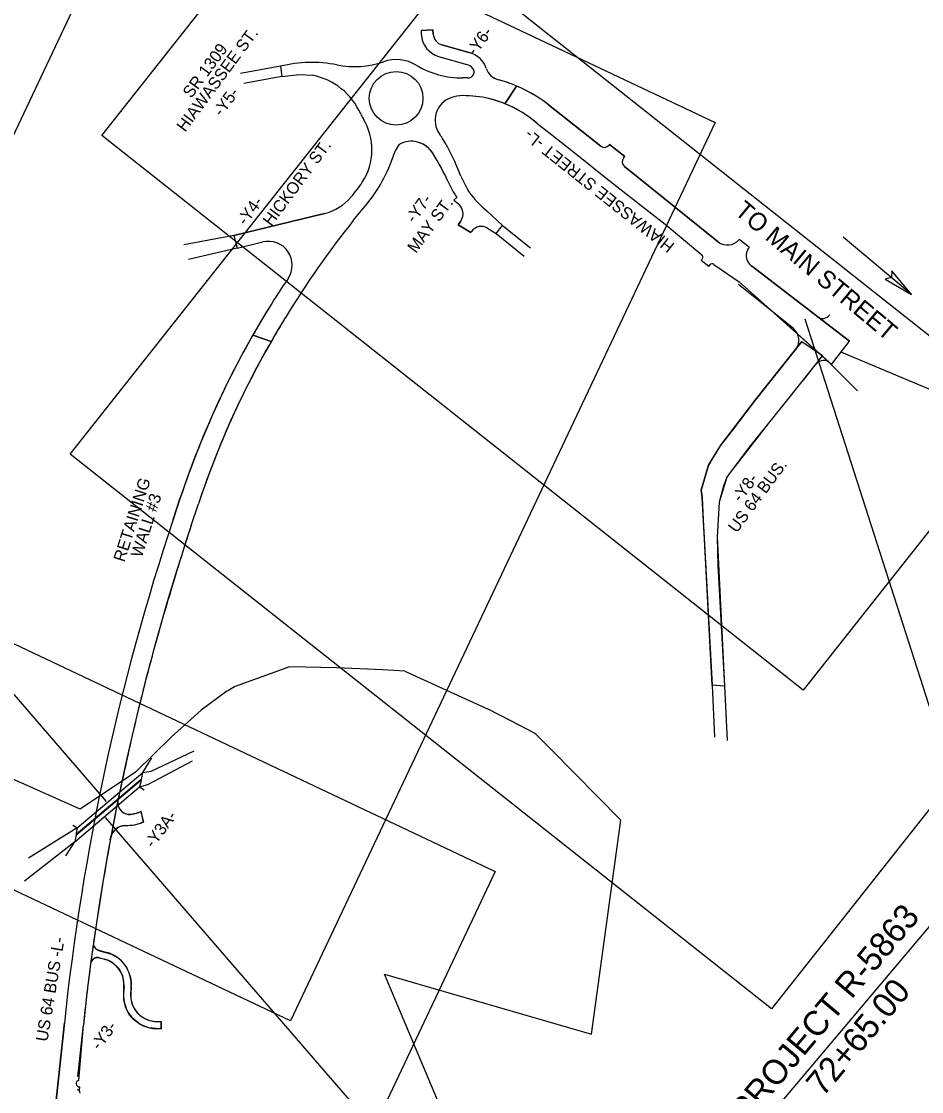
# Model space of a CAD drawing. Extents: x 555292 to 2368606, y 503623 to 1171444.
# Drawn here: x 2361051 to 2362561, y 1164815 to 1166609 of the extents above; entities that cross this region are included whole.
import ezdxf

# ---------------------------------------------------------------- set-up
doc = ezdxf.new("R2010")
doc.units = 0
for name, color, linetype in [('Exist Hydro Stream or Body of Water', 7, 'Continuous'), ('Exist Roads EOT', 7, 'Continuous'), ('Old_Level_48', 7, 'Continuous'), ('Prop DSN Text', 7, 'Continuous'), ('Prop EOT', 7, 'Continuous'), ('Prop Horizontal Alignment Station Label', 7, 'Continuous'), ('Prop Roadway Culvert', 7, 'Continuous'), ('Prop Shade Light', 7, 'Continuous'), ('Prop Terminator CELL', 7, 'Continuous'), ('Sheet Title CELL', 7, 'Continuous')]:
    doc.layers.add(name, color=color, linetype=linetype)

msp = doc.modelspace()

# ---------------------------------------------------------------- linework, layer by layer
at = {"layer": 'Exist Hydro Stream or Body of Water'}
for p, q in [((2361268.9, 1165352.1), (2361341, 1165386.3)), ((2361263.2, 1165330), (2361338.3, 1165369.6)), ((2361254.8, 1165349.8), (2361268.9, 1165352.1)), ((2361249.5, 1165325.7), (2361263.2, 1165330)), ((2361145, 1165257.1), (2361063.4, 1165206)), ((2361140.7, 1165233.8), (2361056.4, 1165167.9))]:
    msp.add_line(p, q, dxfattribs=at)
at = {"layer": 'Exist Roads EOT'}
for p, q in [((2361485.8, 1166534.3), (2361418.7, 1166522.2)), ((2361488.4, 1166517), (2361424.2, 1166505.6)), ((2361858.1, 1166267.1), (2361905.5, 1166229.8)), ((2361407.8, 1166250.5), (2361323.9, 1166235)), ((2361847.6, 1166253.7), (2361894.7, 1166216)), ((2361413, 1166229.1), (2361331.8, 1166210.2)), ((2362346.2, 1166094.3), (2362254.4, 1166168.4)), ((2362282.4, 1165974.1), (2362350, 1166059.3)), ((2362453.7, 1165990), (2362405.2, 1166038.7)), ((2362363.4, 1166008.1), (2362384.7, 1166035)), ((2362210.1, 1165496.3), (2362213.7, 1165409.2)), ((2362230.6, 1165494.8), (2362235, 1165403.4))]:
    msp.add_line(p, q, dxfattribs=at)
for centre, radius, start, end in [((2362395.4, 1166126.3), 15, 231.9272, 322.728), ((2362330.5, 1166074.8), 25, 321.5477, 51.0718), ((2362396.7, 1166026), 15, 44.846, 141.6227)]:
    msp.add_arc(centre, radius, start, end, dxfattribs=at)
at = {"layer": 'Old_Level_48'}
msp.add_line((2361694.7, 1165519.7), (2361834, 1165456.3), dxfattribs=at)
for points in [[(2361694.7, 1165519.7), (2361657.5, 1165522.1), (2361579.9, 1165525.5), (2361500.9, 1165527.2), (2361409.7, 1165494.3), (2361393.5, 1165484.8), (2361352.7, 1165454.5), (2361302.7, 1165408.9), (2361242.7, 1165350.5), (2361149.7, 1165288.3), (2361031, 1165341.5), (2360829.6, 1165448.4), (2360789.2, 1165475.8), (2360747.2, 1165498.6), (2360709.9, 1165516.4), (2360669.1, 1165527.3), (2360632.5, 1165533.3), (2360405, 1165681.4), (2360333.3, 1165702.6), (2360076, 1165757.3), (2360078.4, 1166102.1)], [(2361778.9, 1164481.9), (2361811.7, 1164558.5), (2361839.3, 1164604.9), (2361978.2, 1164750.1), (2361911.7, 1164752.1), (2361841.9, 1164751.4), (2361800.9, 1164754.1), (2361776.9, 1164762.2), (2361757, 1164781.8), (2361660.4, 1165011.9), (2362007.6, 1164911.3), (2362056.6, 1165270.2), (2361940.1, 1165388.6), (2361913.2, 1165415.1), (2361872.2, 1165436.7), (2361834, 1165456.3)]]:
    msp.add_lwpolyline(points, dxfattribs=at)
at = {"layer": 'Prop DSN Text'}
msp.add_line((2362544.5, 1166151.5), (2362429.9, 1166247.4), dxfattribs=at)
at = {"layer": 'Prop EOT'}
for p, q in [((2361721.7, 1166594.2), (2361741.7, 1166595.2)), ((2361741.7, 1166595.2), (2361742.1, 1166588.2)), ((2361721.7, 1166594.2), (2361722.1, 1166587.1)), ((2361756.6, 1166570), (2361804, 1166556.6)), ((2361751.1, 1166550.8), (2361798.5, 1166537.3)), ((2361485.8, 1166534.3), (2361488.4, 1166517)), ((2361488.4, 1166517), (2361517.8, 1166520.3)), ((2361517.8, 1166520.3), (2361539.5, 1166519.1)), ((2361935.2, 1166469.7), (2362023, 1166400.4)), ((2362037, 1166402), (2362037.8, 1166403)), ((2362037.8, 1166403), (2362063.3, 1166382.8)), ((2362061.2, 1166380.3), (2362063.3, 1166382.8)), ((2362062.8, 1166366.3), (2362214.8, 1166243.8)), ((2361776.9, 1166309.5), (2361781.8, 1166314.1)), ((2361776.9, 1166309.5), (2361783.7, 1166304.2)), ((2361607.9, 1166275.5), (2361624.7, 1166295.6)), ((2361832.5, 1166291.3), (2361858.1, 1166267.1)), ((2361407.8, 1166250.5), (2361559.8, 1166287.4)), ((2361784.2, 1166268.5), (2361788.3, 1166274.6)), ((2361805.1, 1166255.4), (2361784.2, 1166268.5)), ((2361805.1, 1166255.4), (2361806.1, 1166256.9)), ((2361833.3, 1166262.6), (2361847.6, 1166253.7)), ((2361847.6, 1166253.7), (2361858.1, 1166267.1)), ((2361407.8, 1166250.5), (2361413, 1166229.1)), ((2361413, 1166229.1), (2361456.1, 1166239.6)), ((2362214.8, 1166243.8), (2362220, 1166240)), ((2362272.1, 1166231), (2362255.2, 1166243.6)), ((2362193.3, 1166211), (2362191.8, 1166209.1)), ((2362191.8, 1166209.1), (2362204.3, 1166199.1)), ((2362205.9, 1166201.1), (2362204.3, 1166199.1)), ((2362275.7, 1166199.5), (2362440.2, 1166073.1)), ((2362360.5, 1166072.4), (2362282.4, 1165974.1)), ((2362410, 1166034.1), (2362440.2, 1166073.1)), ((2362394.9, 1166049.1), (2362338.6, 1165978)), ((2362282.4, 1165974.1), (2362243.4, 1165923.5)), ((2362338.6, 1165978), (2362304.7, 1165935.6)), ((2362304.7, 1165935.6), (2362272.1, 1165895.4)), ((2362243.4, 1165923.5), (2362223.5, 1165897.9)), ((2362223.5, 1165897.9), (2362210.9, 1165877.7)), ((2362272.1, 1165895.4), (2362240.1, 1165852.9)), ((2362210.9, 1165877.7), (2362204.1, 1165865.1)), ((2362204.1, 1165865.1), (2362191.8, 1165823.2)), ((2362234.4, 1165844.9), (2362229.2, 1165830.3)), ((2362240.1, 1165852.9), (2362234.4, 1165844.9)), ((2362229.2, 1165830.3), (2362221.8, 1165803.5)), ((2361305.9, 1165774.3), (2361317.8, 1165810.3)), ((2362191.8, 1165823.2), (2362193.1, 1165811.3)), ((2362193.1, 1165811.3), (2362194.7, 1165773.4)), ((2361336.2, 1165764.3), (2361348.2, 1165800.2)), ((2362221.8, 1165803.5), (2362220.7, 1165783.4)), ((2362194.7, 1165773.4), (2362210.1, 1165496.3)), ((2362220.7, 1165783.4), (2362218.5, 1165745.3)), ((2362218.5, 1165745.3), (2362219.5, 1165697)), ((2362219.5, 1165697), (2362230.6, 1165494.8)), ((2361213, 1165301), (2361213.3, 1165303.5)), ((2361213.3, 1165303.5), (2361214.1, 1165307)), ((2361213, 1165299.2), (2361213, 1165301)), ((2361225.9, 1165280.8), (2361223.7, 1165281.8)), ((2361228.3, 1165280.1), (2361225.9, 1165280.8)), ((2361230.6, 1165279.7), (2361228.3, 1165280.1)), ((2361233.4, 1165279.5), (2361230.6, 1165279.7)), ((2361236, 1165279.7), (2361233.4, 1165279.5)), ((2361239.9, 1165280.4), (2361236, 1165279.7)), ((2361243.4, 1165281.3), (2361239.9, 1165280.4)), ((2361246.3, 1165282.2), (2361243.4, 1165281.3)), ((2361250.1, 1165283.6), (2361246.3, 1165282.2)), ((2361204.2, 1165248.6), (2361206.8, 1165252.1)), ((2361206.8, 1165252.1), (2361209.5, 1165255)), ((2361209.5, 1165255), (2361214.6, 1165258.5)), ((2361214.6, 1165258.5), (2361218.5, 1165259.9)), ((2361218.5, 1165259.9), (2361223.3, 1165260.9)), ((2361223.3, 1165260.9), (2361228.7, 1165260.9)), ((2361228.7, 1165260.9), (2361235.5, 1165261.4)), ((2361235.5, 1165261.4), (2361241.6, 1165262.3)), ((2361241.6, 1165262.3), (2361247.4, 1165263.6)), ((2361247.4, 1165263.6), (2361252.2, 1165265.1)), ((2361200.4, 1165237.1), (2361201.5, 1165241.9)), ((2361201.5, 1165241.9), (2361202.8, 1165245.8)), ((2361202.8, 1165245.8), (2361204.2, 1165248.6)), ((2361181, 1165051.9), (2361194.6, 1165048.2)), ((2361182.5, 1165039.1), (2361191.4, 1165036.6)), ((2361223.5, 1164991.2), (2361222.8, 1164980.1)), ((2361235.5, 1164990.4), (2361234.7, 1164979.3)), ((2361081.5, 1164531.4), (2361123.4, 1164929.8)), ((2361146.2, 1164840.3), (2361155.3, 1164926.4)), ((2361277.7, 1164932.3), (2361285.9, 1164932.1)), ((2361285.7, 1164920.1), (2361285.9, 1164932.1)), ((2361277.5, 1164920.3), (2361285.7, 1164920.1))]:
    msp.add_line(p, q, dxfattribs=at)
for points in [[(2361916.6, 1166438.5), (2361938.3, 1166421.3), (2361967.3, 1166398.4), (2361994.2, 1166377.2), (2362023.4, 1166354), (2362050.3, 1166332.8), (2362078.1, 1166310.8), (2362103.6, 1166290.9), (2362130.9, 1166269.5), (2362192.5, 1166218.1)], [(2362212.9, 1166201.9), (2362255.1, 1166172.5), (2362410.8, 1166034)]]:
    msp.add_lwpolyline(points, dxfattribs=at)
msp.add_circle((2361679.9, 1166480.5), 45, dxfattribs=at)
for centre, radius, start, end in [((2361762.1, 1166589.3), 40, 183.1076, 254.1712), ((2361762.1, 1166589.3), 20, 183.1076, 254.1712), ((2361609.7, 1166683.7), 150, 258.8531, 289.0673), ((2361679.9, 1166480.5), 65, 59.0027, 109.0673), ((2361793.1, 1166518.1), 40, 18.5083, 74.1712), ((2361538.1, 1166320.7), 220, 78.8531, 103.7728), ((2361790.6, 1166664.8), 150, 239.0027, 270.4946), ((2361793.1, 1166518.1), 20, 41.3275, 74.1712), ((2361800.6, 1166524.7), 10, 268.3516, 41.3275), ((2361859.5, 1166540.3), 30, 198.5083, 255.2698), ((2361517.9, 1166409.2), 112, 23.753, 78.8587), ((2361793.9, 1166290.8), 224, 88.3516, 90.4946), ((2361793.9, 1166290.8), 228, 51.6978, 75.2698), ((2361785.2, 1166443.8), 40, 109.6905, 215.064), ((2361791.9, 1166425), 60, 89.7953, 109.6905), ((2361791.4, 1166280), 205, 77.6543, 89.7953), ((2361785.4, 1166282.8), 203.6, 49.8846, 75.841), ((2361679.9, 1166480.5), 65, 203.753, 211.483), ((2361539.2, 1166394.3), 100, 327.065, 31.483), ((2361411.9, 1166181.9), 416, 33.7869, 35.064), ((2361735.3, 1166365.1), 63.1, 142.8651, 165.4235), ((2361705.1, 1166367.8), 40.7, 74.6017, 119.6398), ((2361704, 1166363.7), 45, 57.8217, 74.6017), ((2361704, 1166363.7), 45, 31.9071, 57.8217), ((2361400.7, 1166199.6), 416, 21.2102, 30.8969), ((2362029.2, 1166408.2), 10, 231.6978, 321.6978), ((2361425, 1166468.3), 264, 319.1423, 340.6981), ((2361411.9, 1166181.9), 389, 24.0786, 31.9071), ((2362069.1, 1166374.1), 10, 141.6978, 231.1273), ((2362030.3, 1166456), 264, 203.6499, 210.1439), ((2361425, 1166468.3), 236, 319.5694, 327.065), ((2361927.8, 1166412.4), 176, 204.0786, 213.9528), ((2361539.7, 1166370), 85, 283.6556, 319.8234), ((2361927.8, 1166412.4), 154, 215.2796, 231.806), ((2361770.1, 1166286.9), 22, 325.8636, 51.7277), ((2362765, 1165345.2), 1484.6, 141.1996, 148.8391), ((2361822.7, 1166245.7), 20, 58.0415, 145.8636), ((2361465.6, 1166200.7), 40, 325.8082, 103.6556), ((2362235.7, 1166260), 25.5, 231.8602, 319.944), ((2362288.9, 1166217), 21.9, 140.3179, 232.7247), ((2362189.4, 1166214.1), 5, 321.6978, 51.6978), ((2362209.8, 1166198), 5, 51.6978, 141.6978), ((2362752.2, 1165326.6), 1515.5, 145.8082, 147.9767), ((2362756.6, 1165332.7), 1516, 148.2608, 161.6362), ((2362756.6, 1165332.7), 1484, 148.26, 161.6362), ((2365117.3, 1164509.1), 4016, 161.6362, 173.9875), ((2363260.8, 1165113.4), 2031.6, 161.3151, 163.1218), ((2365398.3, 1164422.5), 4277.8, 162.5789, 164.3855), ((2365201, 1164487.8), 4070.3, 164.5236, 166.3302), ((2365756.5, 1164366.7), 4638.6, 166.4981, 168.3048), ((2361231.5, 1165298.7), 18.5, 178.3283, 245.3599), ((2361351, 1165038.8), 264.7, 111.9713, 112.379), ((2364526.1, 1166011.8), 3354, 192.5284, 192.8399), ((2361445.9, 1164737.1), 562.4, 109.7379, 110.1456), ((2366637.3, 1164261.5), 5523.7, 169.8272, 171.6339), ((2361184.2, 1165063.5), 12, 171.9768, 254.5145), ((2361179.3, 1165027.5), 12, 74.5145, 172.5009), ((2361179.6, 1164994.2), 44, 356.0585, 74.5145), ((2361179.6, 1164994.2), 56, 356.0585, 74.5145), ((2365117.3, 1164509.1), 3984, 172.5578, 173.9875), ((2361278.6, 1164976.3), 56, 176.0585, 268.8266), ((2361278.6, 1164976.3), 44, 176.0585, 268.8266)]:
    msp.add_arc(centre, radius, start, end, dxfattribs=at)
at = {"layer": 'Prop Horizontal Alignment Station Label'}
for p, q in [((2362365.6, 1166110.7), (2362659.7, 1165192.7)), ((2363265.2, 1165701.7), (2362427.6, 1166054.4)), ((2361194.1, 1165301.2), (2360578.7, 1166013.6)), ((2361619.3, 1164780), (2361192.1, 1165274.5)), ((2362128.7, 1164563.4), (2362659.7, 1165192.7))]:
    msp.add_line(p, q, dxfattribs=at)
at = {"layer": 'Prop Roadway Culvert'}
for p, q in [((2361254.8, 1165349.8), (2361270.1, 1165374.5)), ((2361145, 1165257.1), (2361254.8, 1165349.8)), ((2361140.7, 1165233.8), (2361249.5, 1165325.7)), ((2361142.7, 1165244.7), (2361251.9, 1165336.9)), ((2361143, 1165246.2), (2361252.3, 1165338.5)), ((2361249.5, 1165325.7), (2361257.1, 1165321)), ((2361137.5, 1165261.7), (2361145, 1165257.1)), ((2361126, 1165210.1), (2361140.7, 1165233.8))]:
    msp.add_line(p, q, dxfattribs=at)
for centre, radius, start, end in [((2365133.2, 1164492.8), 3972, 167.5396, 167.8948), ((2365104.1, 1164515), 4028, 169.3836, 169.72)]:
    msp.add_arc(centre, radius, start, end, dxfattribs=at)
at = {"layer": 'Prop Shade Light'}
for p, q in [((2361741.7, 1166595.2), (2361721.7, 1166594.2)), ((2361742.1, 1166588.2), (2361741.7, 1166595.2)), ((2361721.7, 1166594.2), (2361722.1, 1166587.1)), ((2361804, 1166556.6), (2361756.6, 1166570)), ((2361751.1, 1166550.8), (2361798.5, 1166537.3)), ((2361485.8, 1166534.3), (2361488.4, 1166517)), ((2361488.4, 1166517), (2361517.8, 1166520.3)), ((2361517.8, 1166520.3), (2361539.5, 1166519.1)), ((2361881.8, 1166501.1), (2361862, 1166471.5)), ((2361862, 1166471.5), (2361881.8, 1166501.1)), ((2362023, 1166400.4), (2361935.2, 1166469.7)), ((2362037.8, 1166403), (2362037, 1166402)), ((2362063.3, 1166382.8), (2362037.8, 1166403)), ((2362061.2, 1166380.3), (2362063.3, 1166382.8)), ((2362214.8, 1166243.8), (2362062.8, 1166366.3)), ((2361781.8, 1166314.1), (2361776.9, 1166309.5)), ((2361776.9, 1166309.5), (2361783.7, 1166304.2)), ((2361607.9, 1166275.5), (2361624.7, 1166295.6)), ((2361858.1, 1166267.1), (2361832.5, 1166291.3)), ((2361559.8, 1166287.4), (2361407.8, 1166250.5)), ((2361788.3, 1166274.6), (2361784.2, 1166268.5)), ((2361784.2, 1166268.5), (2361805.1, 1166255.4)), ((2361805.1, 1166255.4), (2361806.1, 1166256.9)), ((2361833.3, 1166262.6), (2361847.6, 1166253.7)), ((2361847.6, 1166253.7), (2361858.1, 1166267.1)), ((2361407.8, 1166250.5), (2361413, 1166229.1)), ((2361413, 1166229.1), (2361456.1, 1166239.6)), ((2362220, 1166240), (2362214.8, 1166243.8)), ((2362272.1, 1166231), (2362255.2, 1166243.6)), ((2362193.3, 1166211), (2362191.8, 1166209.1)), ((2362191.8, 1166209.1), (2362204.3, 1166199.1)), ((2362204.3, 1166199.1), (2362205.9, 1166201.1)), ((2362440.2, 1166073.1), (2362275.7, 1166199.5)), ((2361470.1, 1166072.4), (2361439.3, 1166083.1)), ((2361439.3, 1166083.1), (2361470.1, 1166072.4)), ((2362410, 1166034.1), (2362440.2, 1166073.1)), ((2361317.8, 1165810.3), (2361305.9, 1165774.3)), ((2361336.2, 1165764.3), (2361348.2, 1165800.2)), ((2361213.3, 1165303.5), (2361201.1, 1165240.5)), ((2361256, 1165266.5), (2361252, 1165284.3)), ((2361123.4, 1164929.8), (2361103.1, 1164737)), ((2361147.7, 1164833.9), (2361155.3, 1164926.4)), ((2361145.4, 1164818.3), (2361148.9, 1164816.4)), ((2361148.9, 1164816.4), (2361149.1, 1164822.7))]:
    msp.add_line(p, q, dxfattribs=at)
for points in [[(2361644.1, 1166453.2), (2361644.1, 1166453.2)], [(2361916.6, 1166438.5), (2361938.3, 1166421.3), (2361967.3, 1166398.4), (2361994.2, 1166377.2), (2362023.4, 1166354), (2362050.3, 1166332.8), (2362078.1, 1166310.8), (2362103.6, 1166290.9), (2362130.9, 1166269.5), (2362192.5, 1166218.1)], [(2362212.9, 1166201.9), (2362255.1, 1166172.5), (2362410, 1166034.1)], [(2361467.3, 1166130.2), (2361467.3, 1166130.2)], [(2361494.5, 1166113.4), (2361494.5, 1166113.4)]]:
    msp.add_lwpolyline(points, dxfattribs=at)
for points in [[(2362360.5, 1166072.4), (2362394.9, 1166049.1), (2362338.6, 1165978), (2362304.7, 1165935.6), (2362240.1, 1165852.9), (2362234.4, 1165844.9), (2362221.8, 1165803.5), (2362218.5, 1165745.3), (2362230.6, 1165494.8), (2362210.1, 1165496.3), (2362197.1, 1165741.3), (2362193.1, 1165811.3), (2362191.8, 1165823.2), (2362204.1, 1165865.1), (2362224.7, 1165898.9), (2362282.4, 1165974.1)], [(2361168.4, 1165032.5), (2361172, 1165060.7), (2361173.5, 1165057.4), (2361177, 1165053.3), (2361184, 1165050.5), (2361202.8, 1165045.4), (2361215.3, 1165037.8), (2361225.4, 1165027), (2361231.1, 1165015.6), (2361234.5, 1165006.3), (2361235.5, 1164997.9), (2361234.5, 1164977.5), (2361234.8, 1164970.4), (2361236.5, 1164962.7), (2361241, 1164952.9), (2361245.7, 1164947), (2361251.3, 1164941.8), (2361259.3, 1164936.6), (2361266.5, 1164933.8), (2361274.7, 1164932.1), (2361285.9, 1164932.1), (2361285.7, 1164920.1), (2361277.5, 1164920.3), (2361265.2, 1164921.9), (2361256, 1164924.9), (2361249.5, 1164928.3), (2361244.1, 1164932.2), (2361236.2, 1164939.5), (2361231.7, 1164945.3), (2361225.8, 1164956.7), (2361223, 1164967.8), (2361222.9, 1164980.1), (2361223.3, 1164996.9), (2361221.5, 1165008.9), (2361215.6, 1165019.8), (2361207, 1165028.7), (2361197.4, 1165034.7), (2361181.3, 1165039.2), (2361178.1, 1165039.1), (2361174.8, 1165038.8), (2361171, 1165036.5)]]:
    msp.add_lwpolyline(points, close=True, dxfattribs=at)
msp.add_circle((2361679.9, 1166480.5), 45, dxfattribs=at)
for centre, radius, start, end in [((2361762.1, 1166589.3), 40, 183.1076, 254.1712), ((2361762.1, 1166589.3), 20, 183.1076, 254.1712), ((2361609.7, 1166683.7), 150, 258.8531, 289.0673), ((2361679.9, 1166480.5), 65, 59.0027, 109.0673), ((2361793.1, 1166518.1), 40, 18.5083, 74.1712), ((2361538.1, 1166320.7), 220, 78.8531, 103.7728), ((2361790.6, 1166664.8), 150, 239.0027, 270.4946), ((2361793.1, 1166518.1), 20, 41.3275, 74.1712), ((2361800.6, 1166524.7), 10, 268.3516, 41.3275), ((2361859.5, 1166540.3), 30, 198.5083, 255.2698), ((2361517.9, 1166409.2), 112, 23.753, 78.8587), ((2361793.9, 1166290.8), 224, 88.3516, 90.4946), ((2361793.9, 1166290.8), 228, 67.3104, 75.2698), ((2361793.9, 1166290.8), 228, 51.6978, 67.3104), ((2361785.2, 1166443.8), 40, 109.6905, 215.064), ((2361791.9, 1166425), 60, 89.7953, 109.6905), ((2361791.4, 1166280), 205, 77.6543, 89.7953), ((2361785.4, 1166282.8), 203.6, 67.8958, 75.841), ((2361785.4, 1166282.8), 203.6, 49.8846, 67.8958), ((2361679.9, 1166480.5), 65, 203.753, 211.483), ((2361539.2, 1166394.3), 100, 327.065, 31.483), ((2361411.9, 1166181.9), 416, 33.7869, 35.064), ((2361735.3, 1166365.1), 63.1, 142.8651, 165.4235), ((2361705.1, 1166367.8), 40.7, 74.6017, 119.6398), ((2361704, 1166363.7), 45, 31.9071, 74.6017), ((2361400.7, 1166199.6), 416, 21.2102, 30.8969), ((2362029.2, 1166408.2), 10, 231.6978, 321.6978), ((2361425, 1166468.3), 264, 319.1423, 340.6981), ((2361411.9, 1166181.9), 389, 24.0786, 31.9071), ((2362069.1, 1166374.1), 10, 141.6978, 231.1273), ((2362030.3, 1166456), 264, 203.6499, 210.1439), ((2361425, 1166468.3), 236, 319.5694, 327.065), ((2361927.8, 1166412.4), 176, 204.0786, 213.9528), ((2361539.7, 1166370), 85, 283.6556, 319.8234), ((2361927.8, 1166412.4), 154, 215.2796, 231.806), ((2361770.1, 1166286.9), 22, 325.8636, 51.7277), ((2362765, 1165345.2), 1484.6, 141.1996, 148.8391), ((2361822.7, 1166245.7), 20, 58.0415, 145.8636), ((2361465.6, 1166200.7), 40, 325.8082, 103.6556), ((2362235.7, 1166260), 25.5, 231.8602, 319.944), ((2362288.9, 1166217), 21.9, 140.3179, 232.7247), ((2362189.4, 1166214.1), 5, 321.6978, 51.6978), ((2362209.8, 1166198), 5, 51.6978, 141.6978), ((2362752.2, 1165326.6), 1515.5, 145.8082, 147.9767), ((2362756.6, 1165332.7), 1516, 148.2608, 150.3316), ((2362756.6, 1165332.7), 1484, 148.26, 150.1046), ((2362756.6, 1165332.7), 1516, 150.3316, 161.6362), ((2362756.6, 1165332.7), 1484, 150.1046, 161.6362), ((2365117.3, 1164509.1), 4016, 161.6362, 173.9875), ((2365117.3, 1164509.1), 3984, 161.6362, 173.9875), ((2361232.9, 1165299.5), 20, 168.4988, 278.6769), ((2361226, 1165345), 66, 278.6769, 293.1688), ((2361225.6, 1165236), 25, 89.8104, 169.4208), ((2361226, 1165345), 84, 269.8104, 290.9044), ((2361148.9, 1164828.3), 5.68, 102.9221, 271.575), ((2361143.1, 1164812), 6.73, 0.6165, 69.7172)]:
    msp.add_arc(centre, radius, start, end, dxfattribs=at)
at = {"layer": 'Prop Terminator CELL'}
msp.add_lwpolyline([(2362500.3, 1166177.2), (2362544.5, 1166151.5), (2362511.4, 1166191), (2362510.6, 1166179.9)], close=True, dxfattribs=at)
at = {"layer": 'Sheet Title CELL'}
for points in [[(2362362.7, 1165487.8), (2361186.1, 1166418.1), (2361837.3, 1167241.7), (2363013.9, 1166311.4)], [(2362215, 1166440), (2361502.8, 1164933.3), (2360548.9, 1165384.2), (2361261.1, 1166890.9)], [(2362309.6, 1164953.5), (2361133, 1165883.8), (2361784.3, 1166707.5), (2362960.9, 1165777.1)], [(2361846.2, 1165184.1), (2361134.1, 1163677.4), (2360180.2, 1164128.3), (2360892.3, 1165635)]]:
    msp.add_lwpolyline(points, close=True, dxfattribs=at)

# ---------------------------------------------------------------- texts
at = {"layer": 'Prop DSN Text'}
for s, height, rotation, p in [('HIAWASSEE ST.', 20, 53.5048, (2361326, 1166422.8)), ('-Y6-', 20, 53.5048, (2361812.3, 1166550.3)), ('SR 1309', 20, 53.5048, (2361336.3, 1166479.4)), ('-Y5-', 20, 53.5048, (2361387.3, 1166448.8)), ('HIAWASSEE STREET -L-', 20, 141.5136, (2362148.4, 1166235.6)), ('HICKORY ST.', 20, 53.5048, (2361470.6, 1166264.6)), ('-Y4-', 20, 53.5048, (2361427.4, 1166265.9)), ('MAY ST.', 20, 53.5048, (2361713.1, 1166219.5)), ('-Y7-', 20, 53.5048, (2361710.3, 1166269.9)), ('TO MAIN STREET', 30, 320.0895, (2362245.9, 1166288)), ('US 64 BUS.', 20, 53.5048, (2362251.2, 1165750.3)), ('RETAINING', 20, 72.3117, (2361224.1, 1165701.6)), ('-Y8-', 20, 53.5048, (2362257.8, 1165801.8)), ('WALL #3', 20, 72.3117, (2361253.1, 1165709)), ('-Y3A-', 20, 53.5048, (2361272.3, 1165221.7)), ('US 64 BUS -L-', 20, 80.5339, (2361094.9, 1164897.6)), ('-Y3-', 20, 53.5048, (2361182.3, 1164883))]:
    msp.add_text(s, height=height, rotation=rotation, dxfattribs=at).set_placement(p)
at = {"layer": 'Prop Horizontal Alignment Station Label'}
for s, p in [('END TIP PROJECT R-5863', (2362118.5, 1164581.2)), ('-L- POT STA. 72+65.00', (2362171.2, 1164537))]:
    msp.add_text(s, height=41.248, rotation=49.9796, dxfattribs=at).set_placement(p)

doc.saveas('drawing.dxf')
